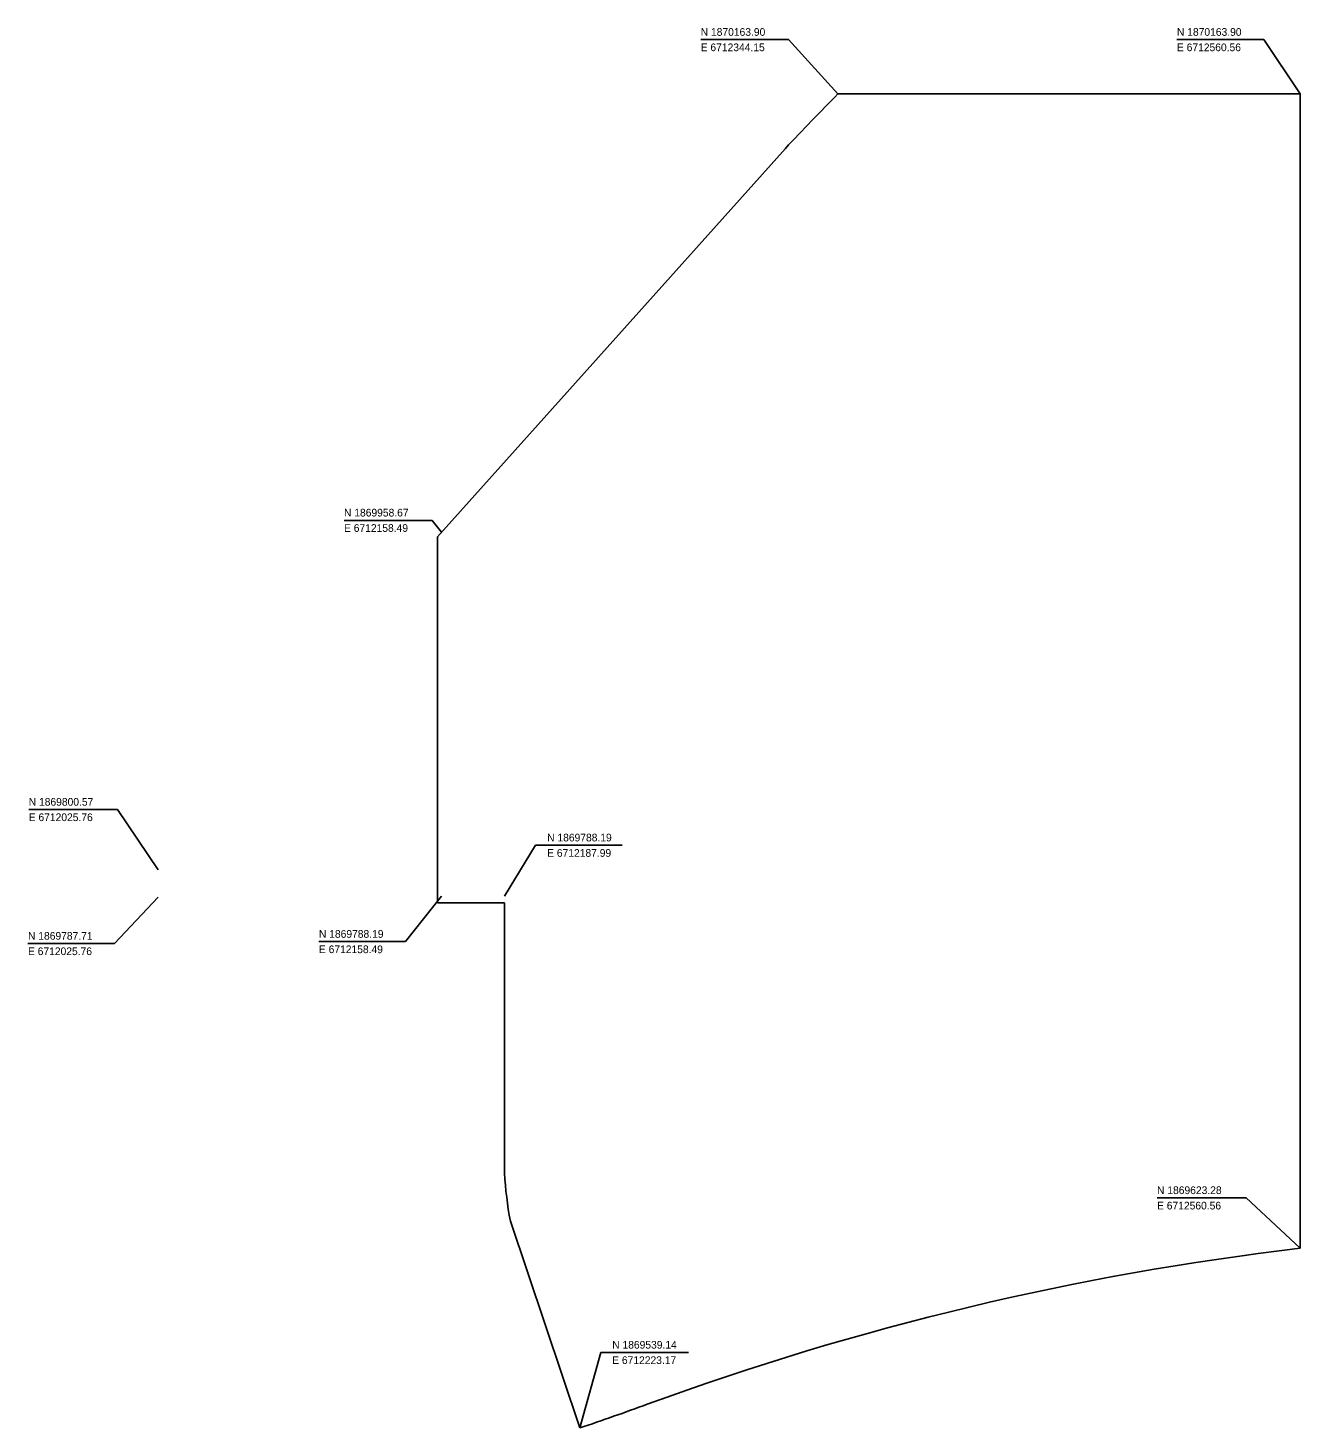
# Model space of a CAD drawing. Extents: x 6711965 to 6712561, y 1869539 to 1870195.
import ezdxf

# ---------------------------------------------------------------- set-up
doc = ezdxf.new("R2010")
doc.units = 0
doc.layers.add('C-COORDS', color=7, linetype='Continuous')
doc.layers.add('Level 15', color=7, linetype='Continuous')

msp = doc.modelspace()

# ---------------------------------------------------------------- linework, layer by layer
at = {"layer": 'C-COORDS'}
for points in [[(6712320.93, 1870189.22), (6712279.85, 1870189.22)], [(6712344.15, 1870163.9), (6712320.93, 1870189.22)], [(6712543.55, 1870189.22), (6712502.92, 1870189.22)], [(6712560.56, 1870163.9), (6712543.55, 1870189.22)], [(6712154.03, 1869964.14), (6712112.77, 1869964.14)], [(6712158.49, 1869958.67), (6712154.03, 1869964.14)], [(6712006.7, 1869828.72), (6711965.1, 1869828.72)], [(6712025.76, 1869800.57), (6712006.7, 1869828.72)], [(6712187.99, 1869788.19), (6712202.52, 1869812)], [(6712202.52, 1869812), (6712243.1, 1869812)], [(6712025.76, 1869787.71), (6712005.33, 1869765.97)], [(6712158.49, 1869788.19), (6712141.6, 1869766.88)], [(6712005.33, 1869765.97), (6711964.75, 1869765.97)], [(6712141.6, 1869766.88), (6712101.02, 1869766.88)], [(6712535.31, 1869646.87), (6712493.6, 1869646.87)], [(6712560.56, 1869623.28), (6712535.31, 1869646.87)], [(6712223.17, 1869539.14), (6712232.99, 1869574.5)], [(6712232.99, 1869574.5), (6712274.16, 1869574.5)]]:
    msp.add_lwpolyline(points, dxfattribs=at)
at = {"layer": 'Level 15'}
for p, q in [((6712560.56, 1870163.9), (6712344.15, 1870163.9)), ((6712560.56, 1869926.78), (6712560.56, 1870163.9)), ((6712319.49, 1870138.29), (6712156.49, 1869956.44)), ((6712560.56, 1869623.28), (6712560.56, 1869926.78)), ((6712156.49, 1869785.01), (6712187.99, 1869785.01)), ((6712187.99, 1869785.01), (6712187.99, 1869658.41)), ((6712190.72, 1869635.97), (6712223.17, 1869539.14))]:
    msp.add_line(p, q, dxfattribs=at)
msp.add_lwpolyline([(6712156.49, 1869956.44), (6712156.49, 1869785.01)], dxfattribs=at)
for centre, radius, start, end in [((6713741.52, 1868793.07), 1957.5, 135.5494, 136.58998), ((6712350.26, 1869666.7), 162.48, 182.92162, 190.89981), ((6712717.46, 1868289.47), 1343, 96.70902, 110.14921), ((6711821.84, 1870730.35), 1257, 288.619, 290.14921)]:
    msp.add_arc(centre, radius, start, end, dxfattribs=at)

# ---------------------------------------------------------------- texts
at = {"layer": 'C-COORDS'}
for s, p in [('N 1870163.90', (6712279.85, 1870191.02)), ('N 1870163.90', (6712502.92, 1870191.02)), ('E 6712344.15', (6712279.85, 1870183.82)), ('E 6712560.56', (6712502.92, 1870183.82)), ('N 1869958.67', (6712112.77, 1869965.94)), ('E 6712158.49', (6712112.77, 1869958.74)), ('N 1869800.57', (6711965.1, 1869830.52)), ('E 6712025.76', (6711965.1, 1869823.32)), ('N 1869788.19', (6712207.92, 1869813.8)), ('E 6712187.99', (6712207.92, 1869806.6)), ('N 1869787.71', (6711964.75, 1869767.77)), ('N 1869788.19', (6712101.02, 1869768.68)), ('E 6712025.76', (6711964.75, 1869760.57)), ('E 6712158.49', (6712101.02, 1869761.48)), ('N 1869623.28', (6712493.6, 1869648.67)), ('E 6712560.56', (6712493.6, 1869641.47)), ('N 1869539.14', (6712238.39, 1869576.3)), ('E 6712223.17', (6712238.39, 1869569.1))]:
    msp.add_text(s, height=3.6, dxfattribs=at).set_placement(p)

doc.saveas('drawing.dxf')
